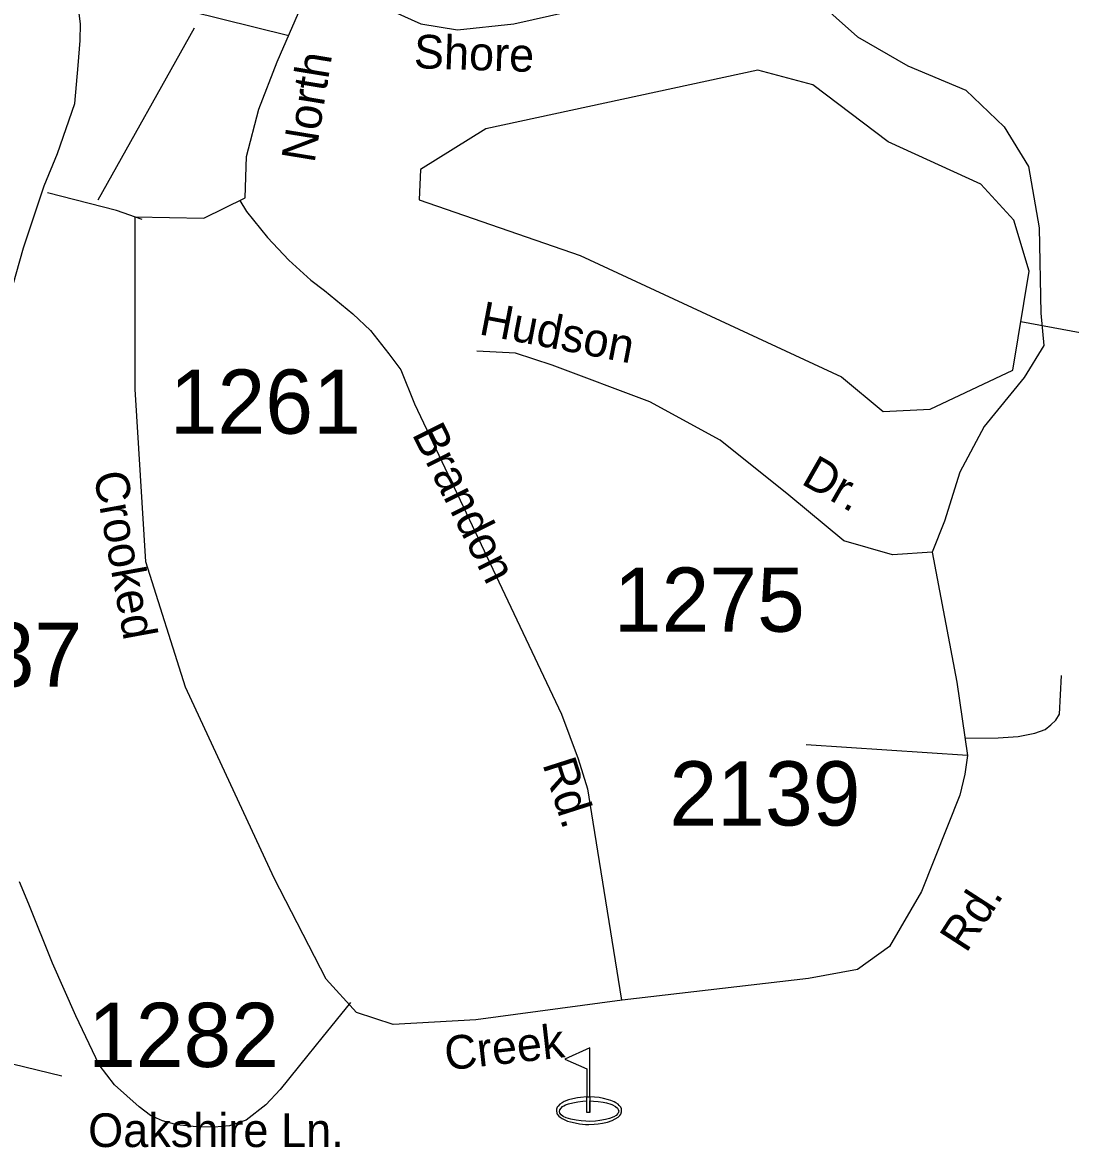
# Model space of a CAD drawing. Extents: x 884530 to 1028605, y 526725 to 653634.
# Drawn here: x 962593 to 964634, y 574324 to 576515 of the extents above; entities that cross this region are included whole.
import ezdxf

# ---------------------------------------------------------------- set-up
doc = ezdxf.new("R2010")
doc.units = 0
for name, color, linetype in [('Exist Cultural Recreational Golf Course CELL', 7, 'Continuous'), ('Exist Hydrographic Bay Label', 7, 'Continuous'), ('Exist Hydrographic Creek Single Shore', 7, 'Continuous'), ('Exist Road Non-System Type 51', 7, 'Continuous'), ('Exist Road Non-System Type 51 Label', 7, 'Continuous'), ('Exist Road Secondary Type 41 Attributed', 7, 'Continuous'), ('Exist Road Secondary Type 51 Attributed', 7, 'Continuous'), ('Exist Road Secondary Type 51 Label', 7, 'Continuous'), ('Exist Road Secondary Type 51 Number Label', 7, 'Continuous')]:
    doc.layers.add(name, color=color, linetype=linetype)

msp = doc.modelspace()

# ---------------------------------------------------------------- linework, layer by layer
at = {"layer": 'Exist Cultural Recreational Golf Course CELL'}
msp.add_lwpolyline([(963697.9, 574518.5), (963649.5, 574496.1), (963692.2, 574477.4), (963692.2, 574422.8), (963697.9, 574422.8), (963697.9, 574415.2), (963697.9, 574392.3), (963697.9, 574415.2), (963705.1, 574414.7), (963714.4, 574413.7), (963724, 574412.5), (963730.4, 574411.2), (963738.9, 574408.7), (963741, 574408), (963747.9, 574404.4), (963751.6, 574401.1), (963753.3, 574398.2), (963754.2, 574395.3), (963754.1, 574393.9), (963753.8, 574392.7), (963753.5, 574391.7), (963752.8, 574390.5), (963749.5, 574386.9), (963744.7, 574384), (963736.4, 574380.8), (963728.3, 574378.6), (963717.5, 574376.9), (963709.2, 574375.7), (963697, 574375.1), (963690.2, 574375.7), (963681.3, 574376.1), (963671.2, 574377.5), (963660.9, 574379.8), (963652, 574382.4), (963646.1, 574385), (963642.4, 574387.9), (963639.8, 574391.5), (963639, 574394.6), (963639.8, 574397.9), (963641.9, 574401.3), (963644.5, 574404.2), (963647.3, 574405.8), (963650.8, 574407.6), (963656.6, 574409.5), (963664.6, 574411.7), (963674.6, 574413.5), (963684.4, 574414.7), (963692.2, 574415.2), (963692.2, 574422.8), (963697.9, 574422.8), (963697.9, 574392.3), (963692.2, 574392.3), (963692.2, 574415.2), (963692.2, 574422.8), (963679.9, 574421.7), (963674, 574421.2), (963664.6, 574419), (963656.8, 574417.1), (963648.2, 574413.7), (963644.4, 574411.5), (963639.6, 574408.5), (963636.5, 574405.2), (963634.5, 574402.7), (963633.3, 574398.9), (963633, 574396), (963633.9, 574391.5), (963634.7, 574389.4), (963637.4, 574385.7), (963640, 574383.5), (963644.2, 574380.6), (963647.8, 574378.8), (963654.6, 574375.9), (963660.4, 574374.4), (963669.6, 574372.2), (963678.1, 574370.5), (963689.3, 574369.5), (963696.4, 574369.2), (963706.7, 574369.8), (963714.4, 574370.5), (963722.5, 574372), (963732.2, 574373.9), (963741.7, 574377.1), (963747.6, 574380.2), (963753.3, 574383.6), (963756.2, 574386.6), (963758.1, 574389.2), (963758.9, 574390.8), (963759.3, 574392.1), (963759.7, 574394), (963760, 574396.1), (963759.5, 574399.5), (963758.2, 574402.7), (963755.1, 574406.5), (963753.2, 574408.6), (963748.7, 574411.6), (963745.1, 574413.6), (963738.8, 574416.2), (963734.5, 574417.4), (963724.4, 574420.1), (963716, 574421.6), (963697.9, 574422.8)], close=True, dxfattribs=at)
at = {"layer": 'Exist Hydrographic Bay Label'}
msp.add_lwpolyline([(964521.7, 575837.9), (964553.6, 576030.9), (964523.6, 576129.9), (964459.3, 576200.1), (964278.6, 576282.5), (964132.4, 576393.8), (964025.1, 576422.2), (963495.7, 576308.1), (963368, 576228.6), (963365.9, 576169.6), (963679.1, 576061.6), (964187.8, 575824.8), (964268.9, 575757.6), (964360.7, 575762.4), (964521.7, 575837.9)], dxfattribs=at)
at = {"layer": 'Exist Hydrographic Creek Single Shore'}
msp.add_lwpolyline([(964537.4, 575932.9), (965037.4, 575840), (965088.5, 575871.8), (965448.1, 576858.9), (966148.1, 578052.5), (966207.3, 578077.6)], dxfattribs=at)
at = {"layer": 'Exist Road Non-System Type 51'}
msp.add_line((963111.8, 576489.3), (962852.6, 576553.6), dxfattribs=at)
for points in [[(962826.1, 576131.2), (962776.6, 576148.9), (962641.8, 576183.5)], [(963016.3, 576168.4), (963029.5, 576146.8), (963070.6, 576096.2), (963111.7, 576052.5), (963154.9, 576013.6), (963181.7, 575993), (963236.6, 575947.7), (963270.8, 575915.6), (963306.6, 575869.7), (963329.8, 575838.6)], [(963329.8, 575838.6), (963356.7, 575772.8), (963445.7, 575584.7), (963643, 575168.4), (963675.2, 575081.5), (963693.2, 575022.7), (963704.1, 574958.2), (963759.5, 574611.6)], [(964429.7, 575121.2), (964493.3, 575122.2), (964531.8, 575124.8), (964564.5, 575131.3), (964584.7, 575138.5), (964595.9, 575147.6), (964605.6, 575156.7), (964612.2, 575168.5), (964616.7, 575243.6)], [(963231.9, 574606.9), (963176.4, 574537.8), (963149, 574503.9), (963094.8, 574437.3), (963067.4, 574407.3), (963028.9, 574377.8), (962996.4, 574366.9), (962966.8, 574364.2), (962932.4, 574364.4), (962893.7, 574368.7), (962866.2, 574376), (962842.8, 574387), (962820.5, 574403.3), (962772.2, 574446.4), (962742.9, 574485.6), (962697.2, 574581), (962651.5, 574683.4), (962605.7, 574798), (962587.6, 574841.8)]]:
    msp.add_lwpolyline(points, dxfattribs=at)
at = {"layer": 'Exist Road Non-System Type 51 Label'}
msp.add_lwpolyline([(962927.8, 576503.8), (962740.2, 576169.4)], dxfattribs=at)
at = {"layer": 'Exist Road Secondary Type 41 Attributed'}
msp.add_lwpolyline([(962567.8, 575979.3), (962595.2, 576076.6), (962630.9, 576183.3), (962635.4, 576197.2), (962661.7, 576260.3), (962695, 576357.3), (962701.5, 576431.5), (962705.9, 576479.9), (962706.4, 576512.8), (962694.9, 576605.3), (962690.5, 576677.9), (962668.5, 576739.6), (962662, 576785.8), (962640, 576828.9), (962611.4, 576883.9), (962593.8, 576930.1), (962554.3, 576989.5)], dxfattribs=at)
at = {"layer": 'Exist Road Secondary Type 51 Attributed'}
for points in [[(964017.1, 576715.2), (964073.5, 576624.4), (964135.9, 576561.9), (964219.2, 576487.5), (964317.3, 576431), (964430.3, 576383.4), (964504.7, 576311.9), (964552.3, 576234.6), (964573.1, 576115.5), (964576.1, 575948.9), (964582, 575886.4), (964543.4, 575823.9), (964466, 575728.7), (964418.5, 575639.4), (964388.7, 575544.2), (964364.9, 575483.4)], [(963217.1, 576581.3), (963368.8, 576512.8), (963440.2, 576500.9), (963550.2, 576512.8), (963657.3, 576536.6)], [(964433.3, 575088), (964428.4, 575051.6), (964418.5, 575010.3), (964344.1, 574822.8), (964281.7, 574715.7), (964219.2, 574671.1), (964124.1, 574653.2), (963761.3, 574611.5), (963475.8, 574572.9), (963315.2, 574563.9), (963243.9, 574587.1), (963184.4, 574652.5), (963083.3, 574848.9), (962910.9, 575220.9), (962833.5, 575464.9), (962812.7, 575801.2), (962812.7, 576137), (962946.6, 576134), (963026.8, 576173.6), (963029.8, 576253.9), (963053.6, 576346.2), (963089.3, 576438.4), (963130.9, 576533.7)], [(964364.9, 575483.4), (964287.6, 575478.7), (964192.4, 575505.5), (964085.4, 575594.8), (963951.6, 575701.9), (963814.8, 575776.3), (963624.5, 575847.7), (963553.1, 575871.5), (963478.1, 575874.9)], [(964364.9, 575483.4), (964412.5, 575230.5), (964433.3, 575088)], [(964433.3, 575088), (964119.4, 575108.2)]]:
    msp.add_lwpolyline(points, dxfattribs=at)
at = {"layer": 'Exist Road Secondary Type 51 Label'}
msp.add_lwpolyline([(962669.9, 574463.6), (962306.4, 574551.6)], dxfattribs=at)

# ---------------------------------------------------------------- texts
at = {"layer": 'Exist Road Non-System Type 51 Label'}
for s, rotation, p in [('Brandon', 296.5358, (963350.7, 575713.9)), ('Rd.', 287.7589, (963605.4, 575071.2))]:
    msp.add_text(s, height=65.62, rotation=rotation, dxfattribs=at).set_placement(p)
at = {"layer": 'Exist Road Secondary Type 51 Label'}
for s, rotation, p in [('Shore', 358.1299, (963354.7, 576426.3)), ('North', 80.7344, (963161.8, 576240)), ('Hudson', 349.1146, (963480.2, 575908.3)), ('Dr.', 330.2836, (964107.3, 575617.9)), ('Crooked', 280.347, (962731.5, 575635.9)), ('Rd.', 57.1756, (964430.9, 574701.4)), ('Creek', 6.3865, (963418.6, 574474.4))]:
    msp.add_text(s, height=65.62, rotation=rotation, dxfattribs=at).set_placement(p)
msp.add_text('Oakshire Ln.', height=65.617, dxfattribs=at).set_placement((962721.2, 574325.3))
at = {"layer": 'Exist Road Secondary Type 51 Number Label'}
for s, p in [('1261', (962880.1, 575714.4)), ('1275', (963744.7, 575328.8)), ('1137', (962337.7, 575221.6)), ('2139', (963853.1, 574951.4)), ('1282', (962720.9, 574481.2))]:
    msp.add_text(s, height=125, dxfattribs=at).set_placement(p)

doc.saveas('drawing.dxf')
